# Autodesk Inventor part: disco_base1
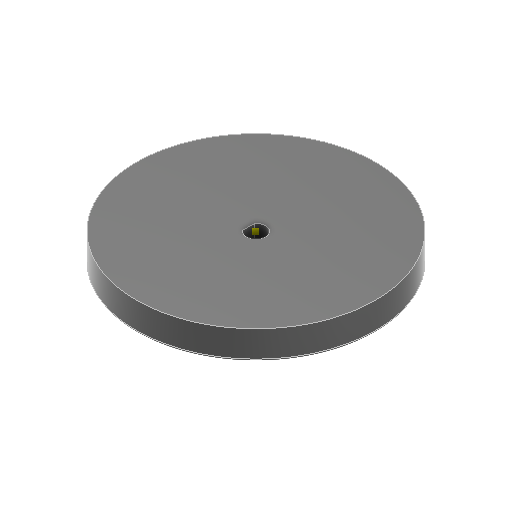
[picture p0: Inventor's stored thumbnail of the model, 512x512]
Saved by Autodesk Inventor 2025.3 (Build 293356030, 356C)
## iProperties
Created: 2026-03
Part Number: disco_base1
Material: Plastica ABS
Document SubType Name: Modeling
Designer: R5800u
Density: 1.06 g/cm^3
Appearance: Liscia - Nero
Author: R5800u
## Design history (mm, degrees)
sketch "Schizzo1"
  geometry: C1 r 10 at (0, 0); C2 r 50 at (0, 0); 1 further point
  constraints: 2 centre point, 2 coincident
  dimensions: "d0" = 20 diameter of C1; "d1" = 100 diameter of C2
extrude "Estrusione1" new body sketch "Schizzo1" distance "d2" = 12; taper "d3" = 0 deg
extrude "Estrusione2" join sketch "Schizzo1" distance "d4" = 6; taper "d5" = 0 deg
sketch "Schizzo3"
  geometry: C1 r 10 at (0, 0) reference; 2 further points
  constraints: 1 coincident
hole "Foro1" sketch "Schizzo3" at (0, 0) diameter "d6" = 8; stored, may be unused: countersink angle "d10" = 90 deg, drill point angle "d12" = 118 deg; dims "d7" = 6, "d8" = 6.5, "d9" = 4.6, "d11" = 11.8
sketch "Schizzo4"
  geometry: C1 r 4 at (0, 0) reference; C2 r 35 at (0, 0); C3 r 10 at (0, 0) reference; C4 r 10 at (0, 0) reference; C5 r 24.5 at (0, 0); 1 further point
  constraints: 2 centre point, 2 coincident
  dimensions: "d13" = 70 diameter of C2; "d16" = 49 diameter of C5
extrude "Estrusione3" cut sketch "Schizzo4" distance "d14" = 5; taper "d15" = 0 deg
fillet "Raccordo1" dims "d17" = 1
sketch "Schizzo5"
  geometry: 1 further point
sketch "Schizzo8"
  geometry: L1 (-3.1, -2.528)-(-3.1, 2.528); A1 r 4 centre (0, 0) between (-3.1, -2.528) and (-3.1, 2.528) reference; 1 further point
  constraints: 2 end point, 2 point on circle, 1 vertical
  dimensions: "d31" = 3.1 distance from line of point (0, 0) L1
extrude "Estrusione5" join sketch "Schizzo8" stored distance "d32" = 5; taper "d33" = 0 deg
node "Solido1"
